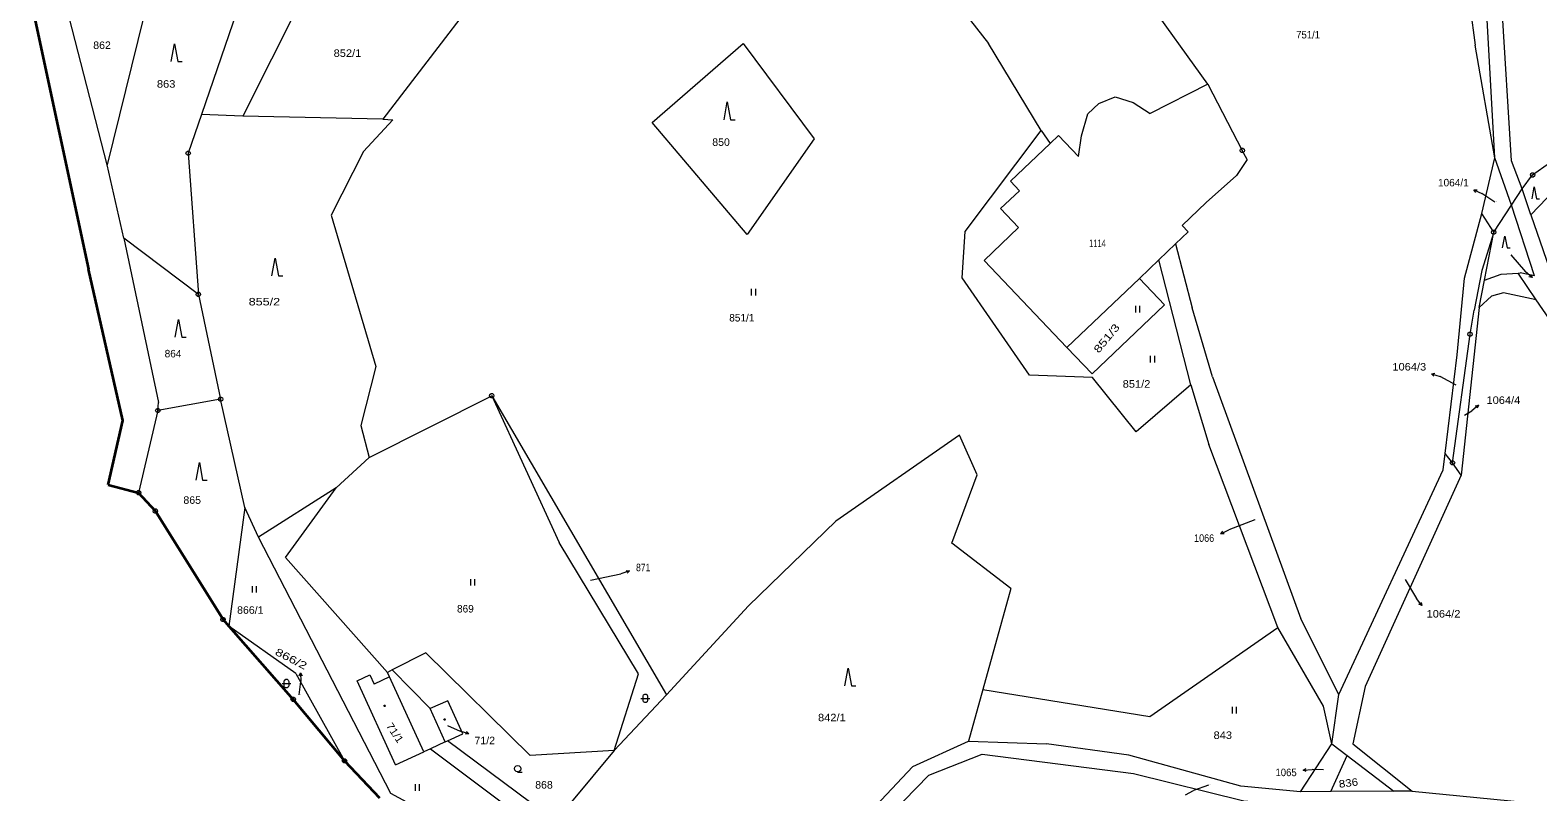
# Model space of a CAD drawing. Extents: x -687390 to -684106, y -954833 to -951648.
# Drawn here: x -687321 to -686980, y -953758.4 to -953586.1 of the extents above; entities that cross this region are included whole.
import ezdxf
from ezdxf.enums import TextEntityAlignment as Align

# ---------------------------------------------------------------- set-up
doc = ezdxf.new("R2010")
doc.units = 0
doc.header["$LTSCALE"] = 0.68
for name, color, linetype, lineweight in [('1', 7, 'Continuous', 13), ('3', 7, 'Continuous', 13), ('4', 7, 'Continuous', 13), ('5', 7, 'Continuous', 13), ('7', 7, 'Continuous', 13), ('8', 7, 'Continuous', 13)]:
    doc.layers.add(name, color=color, linetype=linetype, lineweight=lineweight)
doc.layers.add('2', color=7, linetype='Continuous')

msp = doc.modelspace()

# ---------------------------------------------------------------- linework, layer by layer
at = {"layer": '1'}
for p, q in [((-687122.28, -953566.01), (-687104.26, -953589.16)), ((-687054.67, -953598.36), (-687073.39, -953572.18)), ((-686995.32, -953581.1), (-686994.2, -953589.53)), ((-686989.73, -953615.03), (-686991.62, -953580.99)), ((-687295.24, -953582.94), (-687303.52, -953616.63)), ((-686989.73, -953615.03), (-686994.2, -953589.53)), ((-687054.67, -953598.36), (-687067.72, -953605)), ((-687054.67, -953598.36), (-687046.87, -953613.34)), ((-687071.57, -953602.48), (-687067.72, -953605)), ((-687099.3, -953620.31), (-687090.31, -953611.76)), ((-687088.42, -953609.96), (-687083.89, -953614.72)), ((-687083.89, -953614.72), (-687083.22, -953610.02)), ((-687045.79, -953615.4), (-687048.16, -953618.97)), ((-687045.79, -953615.4), (-687046.87, -953613.34)), ((-686992.69, -953627.63), (-686989.73, -953615.03)), ((-686985.98, -953625.68), (-686989.73, -953615.03)), ((-687299.75, -953633.15), (-687303.52, -953616.63)), ((-687055.01, -953625.1), (-687048.16, -953618.97)), ((-686972.07, -953617.91), (-686981.59, -953627.91)), ((-687101.54, -953626.49), (-687097.28, -953622.44)), ((-687099.3, -953620.31), (-687097.28, -953622.44)), ((-686981.59, -953627.91), (-686983.6, -953622.05)), ((-687101.54, -953626.49), (-687097.45, -953630.78)), ((-686980.79, -953641.68), (-686985.98, -953625.68)), ((-686996.6, -953642.25), (-686992.69, -953627.63)), ((-686990.01, -953631.84), (-686992.69, -953627.63)), ((-686981.59, -953627.91), (-686958.5, -953695.18)), ((-687299.75, -953633.15), (-687291.92, -953670.34)), ((-687105.27, -953638.22), (-687097.45, -953630.78)), ((-687061.95, -953634.5), (-687059.08, -953631.77)), ((-686990.01, -953631.84), (-686992.67, -953640.5)), ((-686992.11, -953642.71), (-686990.01, -953631.84)), ((-687061.95, -953634.5), (-687058.17, -953648.97)), ((-687105.27, -953638.22), (-687086.54, -953657.89)), ((-687070.14, -953642.29), (-687064.46, -953648.25)), ((-686998.3, -953659.55), (-686996.6, -953642.25)), ((-686992.67, -953640.5), (-686994.45, -953649.43)), ((-686992.11, -953642.71), (-686988.33, -953641.36)), ((-686980.39, -953647.15), (-686984.52, -953641.1)), ((-686980.79, -953641.68), (-686984, -953641.06)), ((-687064.46, -953648.25), (-687080.84, -953663.88)), ((-687053.57, -953664.58), (-687058.17, -953648.97)), ((-686995.37, -953654.89), (-686994.45, -953649.43)), ((-687080.84, -953663.88), (-687086.54, -953657.89)), ((-687058.5, -953666.32), (-687054.46, -953679.82)), ((-687053.57, -953664.58), (-687033.66, -953719.27)), ((-687292.1, -953672.19), (-687291.92, -953670.34)), ((-687244.29, -953682.82), (-687216.59, -953668.83)), ((-687216.59, -953668.83), (-687201.33, -953701.99)), ((-687292.1, -953672.19), (-687296.44, -953690.76)), ((-687038.81, -953721.26), (-687054.46, -953679.82)), ((-686999.33, -953684.01), (-687001.03, -953681.87)), ((-687025.07, -953736.37), (-687001.48, -953685.61)), ((-687272.41, -953694.1), (-687276.06, -953720.94)), ((-687177.08, -953736.48), (-687158.53, -953716.37)), ((-687260.9, -953731.67), (-687276.06, -953720.94)), ((-687067.79, -953741.36), (-687038.81, -953721.26)), ((-687260.9, -953731.67), (-687249.88, -953751.4)), ((-687244.16, -953731.95), (-687243.2, -953734.04)), ((-687239.7, -953732.43), (-687240.18, -953731.39)), ((-687239.1, -953730.85), (-687230.48, -953739.6)), ((-687239.7, -953732.43), (-687243.2, -953734.04)), ((-687105.54, -953735.25), (-687067.79, -953741.36)), ((-687226.53, -953737.82), (-687230.48, -953739.6)), ((-687227.1, -953747.12), (-687230.48, -953739.6)), ((-687230.43, -953748.66), (-687203.33, -953768.99)), ((-687227.1, -953747.12), (-687226.6, -953746.9)), ((-687108.81, -953746.95), (-687091.12, -953747.58)), ((-687033.7, -953758.39), (-687026.6, -953747.56)), ((-687238.33, -953752.28), (-687231.94, -953749.35)), ((-687026.82, -953758.35), (-687023.16, -953750.19)), ((-687008.44, -953758.27), (-687012.57, -953758.28))]:
    msp.add_line(p, q, dxfattribs=at)
at = {"layer": '1', "lineweight": 35}
for p, q in [((-687320.97, -953578.62), (-687307.81, -953640.21)), ((-687303.3, -953688.97), (-687296.44, -953690.76)), ((-687292.65, -953694.92), (-687296.44, -953690.76)), ((-687277.36, -953719.45), (-687292.65, -953694.92)), ((-687261.48, -953737.5), (-687249.88, -953751.4)), ((-687249.88, -953751.4), (-687241.94, -953759.8))]:
    msp.add_line(p, q, dxfattribs=at)
at = {"layer": '1'}
for points in [[(-687303.52, -953616.63), (-687313.41, -953578.17), (-687305.51, -953582.02), (-687283.42, -953540.01), (-687248.89, -953494.77)], [(-686983.6, -953622.05), (-686986.01, -953615.7), (-686988.15, -953580.23), (-686986.8, -953544.67), (-686989.72, -953526.06)], [(-687259.89, -953555.79), (-687271.57, -953574.12), (-687282.2, -953605.18), (-687285.23, -953613.98), (-687282.93, -953645.9), (-687299.75, -953633.15)], [(-687209.64, -953564.99), (-687241.21, -953606.29), (-687272.84, -953605.61)], [(-687259.92, -953579.82), (-687272.84, -953605.61), (-687282.2, -953605.18)], [(-687058.5, -953666.32), (-687070.83, -953677), (-687080.73, -953664.72), (-687094.99, -953664.18), (-687110.21, -953642.18), (-687109.53, -953631.68), (-687092.38, -953608.84), (-687104.26, -953589.16)], [(-687083.22, -953610.02), (-687081.77, -953605.09), (-687079.33, -953602.69), (-687075.61, -953601.22), (-687071.57, -953602.48)], [(-687241.21, -953606.29), (-687238.93, -953606.38), (-687245.61, -953613.55), (-687252.92, -953628.01), (-687242.81, -953662.21), (-687246.22, -953675.58), (-687244.29, -953682.82), (-687251.79, -953689.67), (-687269.32, -953700.82), (-687272.41, -953694.1), (-687277.89, -953669.6)], [(-687092.38, -953608.84), (-687090.31, -953611.76), (-687088.42, -953609.96)], [(-686983.6, -953622.05), (-686981.22, -953618.89), (-686972.27, -953612.53)], [(-686990.01, -953631.84), (-686985.98, -953625.68), (-686983.6, -953622.05)], [(-687055.01, -953625.1), (-687060.48, -953630.31), (-687059.08, -953631.77)], [(-687058.5, -953666.32), (-687065.73, -953638.1), (-687061.95, -953634.5)], [(-687086.54, -953657.89), (-687070.14, -953642.29), (-687065.73, -953638.1)], [(-686988.33, -953641.36), (-686984.52, -953641.1), (-686984, -953641.06)], [(-687282.93, -953645.9), (-687277.89, -953669.6), (-687292.1, -953672.19)], [(-686987.83, -953645.51), (-686990.51, -953646.29), (-686993.29, -953648.84), (-686997.39, -953686.82), (-687019.09, -953734.57), (-687021.85, -953747.55), (-687008.44, -953758.27), (-686979.19, -953761.14), (-686963.87, -953771.57), (-686958.4, -953782.31)], [(-686977.42, -953651.49), (-686980.39, -953647.15), (-686987.83, -953645.51)], [(-686997.39, -953686.82), (-686999.33, -953684.01), (-686995.37, -953654.89)], [(-687001.48, -953685.61), (-687001.03, -953681.87), (-686998.3, -953659.55)], [(-687216.59, -953668.83), (-687177.08, -953736.48), (-687188.89, -953749.08), (-687207.88, -953750.21), (-687231.46, -953727.01)], [(-687099.18, -953712.44), (-687112.52, -953702.16), (-687106.8, -953686.69), (-687110.82, -953677.75), (-687138.76, -953697.23), (-687158.53, -953716.37)], [(-687240.18, -953731.39), (-687263.24, -953705.43), (-687251.79, -953689.67)], [(-687186.34, -953779.52), (-687203.33, -953768.99), (-687207.01, -953776.37), (-687239.43, -953758.79), (-687269.32, -953700.82)], [(-687188.89, -953749.08), (-687183.37, -953731.72), (-687201.33, -953701.99)], [(-687099.18, -953712.44), (-687105.54, -953735.25), (-687108.81, -953746.95)], [(-687026.6, -953747.56), (-687028.53, -953739.05), (-687038.81, -953721.26)], [(-687026.6, -953747.56), (-687025.07, -953736.37), (-687033.66, -953719.27)], [(-687231.46, -953727.01), (-687239.1, -953730.85), (-687240.18, -953731.39)], [(-687238.33, -953752.28), (-687247.04, -953733.28), (-687244.16, -953731.95)], [(-687226.6, -953746.9), (-687223.11, -953745.32), (-687226.53, -953737.82)], [(-687227.1, -953747.12), (-687230.43, -953748.66), (-687231.94, -953749.35)], [(-687198.55, -953760.7), (-687201.24, -953765.7), (-687226.6, -953746.9)], [(-687188.89, -953749.08), (-687198.55, -953760.7), (-687173.96, -953778.19)], [(-687161.85, -953777.68), (-687149.8, -953775.92), (-687135.66, -953767.9), (-687121.36, -953752.72), (-687108.81, -953746.95)], [(-687033.7, -953758.39), (-687047.2, -953757.14), (-687072.54, -953750.14), (-687091.12, -953747.58)], [(-687026.6, -953747.56), (-687023.16, -953750.19), (-687012.57, -953758.28)], [(-687148.81, -953779.17), (-687134.53, -953771.88), (-687117.73, -953754.67), (-687105.72, -953749.93), (-687071.47, -953754.3), (-687046.55, -953760.43), (-687028.09, -953761.94)], [(-687012.57, -953758.28), (-687026.82, -953758.35), (-687033.7, -953758.39)]]:
    msp.add_lwpolyline(points, dxfattribs=at)
msp.add_lwpolyline([(-687159.7, -953589.13), (-687143.71, -953610.72), (-687158.81, -953632.33), (-687180.3, -953607.01)], close=True, dxfattribs=at)
at = {"layer": '1', "lineweight": 35}
for points in [[(-687303.3, -953688.97), (-687299.99, -953674.46), (-687307.81, -953640.21)], [(-687277.36, -953719.45), (-687276.06, -953720.94), (-687261.48, -953737.5)]]:
    msp.add_lwpolyline(points, dxfattribs=at)
at = {"layer": '3'}
for p, q in [((-687157.89, -953644.67), (-687157.89, -953646.17)), ((-687156.89, -953646.17), (-687156.89, -953644.67)), ((-687071.01, -953648.49), (-687071.01, -953649.99)), ((-687070.01, -953649.99), (-687070.01, -953648.49)), ((-687067.67, -953659.82), (-687067.67, -953661.32)), ((-687066.67, -953661.32), (-687066.67, -953659.82)), ((-687221.42, -953710.28), (-687221.42, -953711.78)), ((-687220.42, -953711.78), (-687220.42, -953710.28)), ((-687270.76, -953711.86), (-687270.76, -953713.36)), ((-687269.76, -953713.36), (-687269.76, -953711.86)), ((-687049.17, -953739.16), (-687049.17, -953740.66)), ((-687048.17, -953740.66), (-687048.17, -953739.16)), ((-687233.93, -953756.65), (-687233.93, -953758.15)), ((-687232.93, -953758.15), (-687232.93, -953756.65))]:
    msp.add_line(p, q, dxfattribs=at)
for points in [[(-687289.07, -953593.23), (-687288.32, -953589.23), (-687287.57, -953593.23), (-687286.57, -953593.23)], [(-687164.07, -953606.38), (-687163.32, -953602.38), (-687162.57, -953606.38), (-687161.57, -953606.38)], [(-686981.342, -953624.26), (-686980.84, -953621.58), (-686980.338, -953624.26), (-686979.668, -953624.26)], [(-686988.002, -953635.38), (-686987.5, -953632.7), (-686986.998, -953635.38), (-686986.328, -953635.38)], [(-687266.31, -953641.68), (-687265.56, -953637.68), (-687264.81, -953641.68), (-687263.81, -953641.68)], [(-687288.19, -953655.58), (-687287.44, -953651.58), (-687286.69, -953655.58), (-687285.69, -953655.58)], [(-687283.46, -953687.93), (-687282.71, -953683.93), (-687281.96, -953687.93), (-687280.96, -953687.93)], [(-687136.76, -953734.41), (-687136.01, -953730.41), (-687135.26, -953734.41), (-687134.26, -953734.41)], [(-687264.02, -953733.93), (-687262.75, -953733.93), (-687262.02, -953733.93)], [(-687182.85, -953737.27), (-687181.58, -953737.27), (-687180.85, -953737.27)], [(-687210.72, -953753.91), (-687211.1, -953753.81), (-687211.37, -953753.54), (-687211.47, -953753.17), (-687211.37, -953752.8), (-687211.1, -953752.53), (-687210.73, -953752.43), (-687210.36, -953752.53), (-687210.09, -953752.8), (-687209.99, -953753.18), (-687210.09, -953753.56), (-687210.36, -953753.83), (-687210.74, -953753.93), (-687209.74, -953753.93)]]:
    msp.add_lwpolyline(points, dxfattribs=at)
for points in [[(-687263.52, -953733.43), (-687263.42, -953733.14), (-687263.17, -953732.96), (-687262.86, -953732.96), (-687262.61, -953733.14), (-687262.51, -953733.43), (-687262.51, -953734.43), (-687262.61, -953734.72), (-687262.86, -953734.9), (-687263.17, -953734.9), (-687263.42, -953734.72), (-687263.52, -953734.43)], [(-687182.35, -953736.77), (-687182.25, -953736.48), (-687182, -953736.3), (-687181.69, -953736.3), (-687181.44, -953736.48), (-687181.34, -953736.77), (-687181.34, -953737.77), (-687181.44, -953738.06), (-687181.69, -953738.24), (-687182, -953738.24), (-687182.25, -953738.06), (-687182.35, -953737.77)]]:
    msp.add_lwpolyline(points, close=True, dxfattribs=at)
at = {"layer": '4'}
for p, q in [((-686993.29, -953648.84), (-686992.11, -953642.71)), ((-687231.94, -953749.35), (-687239.7, -953732.43))]:
    msp.add_line(p, q, dxfattribs=at)
at = {"layer": '5'}
for points in [[(-687240.73, -953738.8), (-687240.64, -953738.95), (-687240.73, -953739.1), (-687240.91, -953739.1), (-687241, -953738.95), (-687240.91, -953738.8)], [(-687227.17, -953741.87), (-687227.08, -953742.02), (-687227.17, -953742.17), (-687227.35, -953742.17), (-687227.44, -953742.02), (-687227.35, -953741.87)]]:
    msp.add_lwpolyline(points, close=True, dxfattribs=at)
at = {"layer": '7'}
for p, q in [((-686994.491, -953622.26), (-686992.67, -953623.11)), ((-686989.76, -953625.01), (-686992.67, -953623.11)), ((-686986.16, -953636.92), (-686982.84, -953640.78)), ((-686981.327, -953642.103), (-686982.84, -953640.78)), ((-687004.048, -953663.838), (-687002.15, -953664.5)), ((-686998.47, -953666.4), (-687002.15, -953664.5)), ((-686996.65, -953673.23), (-686995, -953672.22)), ((-686993.447, -953670.944), (-686995, -953672.22)), ((-687044, -953696.87), (-687049.95, -953699.12)), ((-687051.712, -953700.088), (-687049.95, -953699.12)), ((-687194.29, -953710.51), (-687187.37, -953709.11)), ((-687185.476, -953708.437), (-687187.37, -953709.11)), ((-687010.07, -953710.35), (-687007.5, -953714.72)), ((-687006.246, -953716.291), (-687007.5, -953714.72)), ((-687259.81, -953731.48), (-687259.77, -953733.49)), ((-687260.13, -953736.5), (-687259.77, -953733.49)), ((-687226.63, -953743.38), (-687223.7, -953744.71)), ((-687221.771, -953745.274), (-687223.7, -953744.71)), ((-687033.092, -953753.505), (-687031.09, -953753.33)), ((-687028.51, -953753.47), (-687031.09, -953753.33)), ((-687059.712, -953759.058), (-687057.94, -953758.11)), ((-687054.54, -953756.87), (-687057.94, -953758.11))]:
    msp.add_line(p, q, dxfattribs=at)
for points in [[(-686994.026, -953622.847), (-686994.491, -953622.26), (-686993.742, -953622.24)], [(-686981.611, -953641.41), (-686981.327, -953642.103), (-686982.052, -953641.914)], [(-687003.526, -953664.375), (-687004.048, -953663.838), (-687003.305, -953663.742)], [(-686994.177, -953671.111), (-686993.447, -953670.944), (-686993.752, -953671.628)], [(-687050.963, -953700.059), (-687051.712, -953700.088), (-687051.286, -953699.471)], [(-687186.22, -953708.345), (-687185.476, -953708.437), (-687185.995, -953708.977)], [(-687006.402, -953715.559), (-687006.246, -953716.291), (-687006.926, -953715.976)], [(-687260.132, -953732.157), (-687259.81, -953731.48), (-687259.462, -953732.144)], [(-687222.32, -953744.764), (-687221.771, -953745.274), (-687222.508, -953745.408)], [(-687032.396, -953753.78), (-687033.092, -953753.505), (-687032.454, -953753.113)]]:
    msp.add_lwpolyline(points, dxfattribs=at)
at = {"layer": '8'}
for p, q in [((-687285.35, -953613.98), (-687285.11, -953613.98)), ((-687046.99, -953613.34), (-687046.75, -953613.34)), ((-686981.34, -953618.89), (-686981.1, -953618.89)), ((-686990.13, -953631.84), (-686989.89, -953631.84)), ((-687283.05, -953645.9), (-687282.81, -953645.9)), ((-686995.49, -953654.89), (-686995.25, -953654.89)), ((-687278.01, -953669.6), (-687277.77, -953669.6)), ((-687216.71, -953668.83), (-687216.47, -953668.83)), ((-687292.22, -953672.19), (-687291.98, -953672.19)), ((-686999.45, -953684.01), (-686999.21, -953684.01)), ((-687296.56, -953690.76), (-687296.32, -953690.76)), ((-687292.77, -953694.92), (-687292.53, -953694.92)), ((-687277.48, -953719.45), (-687277.24, -953719.45)), ((-687261.6, -953737.5), (-687261.36, -953737.5)), ((-687250, -953751.4), (-687249.76, -953751.4))]:
    msp.add_line(p, q, dxfattribs=at)
for points in [[(-687046.72, -953612.86), (-687046.47, -953613.04), (-687046.37, -953613.33), (-687046.47, -953613.62), (-687046.72, -953613.8), (-687047.03, -953613.8), (-687047.28, -953613.62), (-687047.38, -953613.33), (-687047.28, -953613.04), (-687047.03, -953612.86)], [(-687285.08, -953613.5), (-687284.83, -953613.68), (-687284.73, -953613.97), (-687284.83, -953614.26), (-687285.08, -953614.44), (-687285.39, -953614.44), (-687285.64, -953614.26), (-687285.74, -953613.97), (-687285.64, -953613.68), (-687285.39, -953613.5)], [(-686981.07, -953618.41), (-686980.82, -953618.59), (-686980.72, -953618.88), (-686980.82, -953619.17), (-686981.07, -953619.35), (-686981.38, -953619.35), (-686981.63, -953619.17), (-686981.73, -953618.88), (-686981.63, -953618.59), (-686981.38, -953618.41)], [(-686989.86, -953631.36), (-686989.61, -953631.54), (-686989.51, -953631.83), (-686989.61, -953632.12), (-686989.86, -953632.3), (-686990.17, -953632.3), (-686990.42, -953632.12), (-686990.52, -953631.83), (-686990.42, -953631.54), (-686990.17, -953631.36)], [(-687282.78, -953645.42), (-687282.53, -953645.6), (-687282.43, -953645.89), (-687282.53, -953646.18), (-687282.78, -953646.36), (-687283.09, -953646.36), (-687283.34, -953646.18), (-687283.44, -953645.89), (-687283.34, -953645.6), (-687283.09, -953645.42)], [(-686995.22, -953654.41), (-686994.97, -953654.59), (-686994.87, -953654.88), (-686994.97, -953655.17), (-686995.22, -953655.35), (-686995.53, -953655.35), (-686995.78, -953655.17), (-686995.88, -953654.88), (-686995.78, -953654.59), (-686995.53, -953654.41)], [(-687277.74, -953669.12), (-687277.49, -953669.3), (-687277.39, -953669.59), (-687277.49, -953669.88), (-687277.74, -953670.06), (-687278.05, -953670.06), (-687278.3, -953669.88), (-687278.4, -953669.59), (-687278.3, -953669.3), (-687278.05, -953669.12)], [(-687216.44, -953668.35), (-687216.19, -953668.53), (-687216.09, -953668.82), (-687216.19, -953669.11), (-687216.44, -953669.29), (-687216.75, -953669.29), (-687217, -953669.11), (-687217.1, -953668.82), (-687217, -953668.53), (-687216.75, -953668.35)], [(-687291.95, -953671.71), (-687291.7, -953671.89), (-687291.6, -953672.18), (-687291.7, -953672.47), (-687291.95, -953672.65), (-687292.26, -953672.65), (-687292.51, -953672.47), (-687292.61, -953672.18), (-687292.51, -953671.89), (-687292.26, -953671.71)], [(-686999.18, -953683.53), (-686998.93, -953683.71), (-686998.83, -953684), (-686998.93, -953684.29), (-686999.18, -953684.47), (-686999.49, -953684.47), (-686999.74, -953684.29), (-686999.84, -953684), (-686999.74, -953683.71), (-686999.49, -953683.53)], [(-687296.29, -953690.28), (-687296.04, -953690.46), (-687295.94, -953690.75), (-687296.04, -953691.04), (-687296.29, -953691.22), (-687296.6, -953691.22), (-687296.85, -953691.04), (-687296.95, -953690.75), (-687296.85, -953690.46), (-687296.6, -953690.28)], [(-687292.5, -953694.44), (-687292.25, -953694.62), (-687292.15, -953694.91), (-687292.25, -953695.2), (-687292.5, -953695.38), (-687292.81, -953695.38), (-687293.06, -953695.2), (-687293.16, -953694.91), (-687293.06, -953694.62), (-687292.81, -953694.44)], [(-687277.21, -953718.97), (-687276.96, -953719.15), (-687276.86, -953719.44), (-687276.96, -953719.73), (-687277.21, -953719.91), (-687277.52, -953719.91), (-687277.77, -953719.73), (-687277.87, -953719.44), (-687277.77, -953719.15), (-687277.52, -953718.97)], [(-687261.33, -953737.02), (-687261.08, -953737.2), (-687260.98, -953737.49), (-687261.08, -953737.78), (-687261.33, -953737.96), (-687261.64, -953737.96), (-687261.89, -953737.78), (-687261.99, -953737.49), (-687261.89, -953737.2), (-687261.64, -953737.02)], [(-687249.73, -953750.92), (-687249.48, -953751.1), (-687249.38, -953751.39), (-687249.48, -953751.68), (-687249.73, -953751.86), (-687250.04, -953751.86), (-687250.29, -953751.68), (-687250.39, -953751.39), (-687250.29, -953751.1), (-687250.04, -953750.92)]]:
    msp.add_lwpolyline(points, close=True, dxfattribs=at)

# ---------------------------------------------------------------- texts
at = {"layer": '2'}
for s, height, width, p in [('862', 1.7, 1.05, (-687306.705, -953590.39)), ('751/1', 1.7, 0.95, (-687034.685, -953588.01)), ('852/1', 1.7, 1.1, (-687252.345, -953592.18)), ('863', 1.7, 1.1, (-687292.305, -953599.15)), ('850', 1.7, 1.05, (-687166.725, -953612.31)), ('1114', 1.7, 0.65, (-687081.495, -953635.19)), ('834/2', 0.1, 1.25, (-686986.132, -953636.92)), ('855/2', 1.7, 1.25, (-687271.555, -953648.4)), ('851/2', 1.7, 1.1, (-687073.915, -953667)), ('1064/3', 0.1, 1.1, (-686998.424, -953666.4)), ('1064/4', 0.1, 1.1, (-686996.604, -953673.23)), ('865', 1.7, 1.05, (-687286.315, -953693.27)), ('1066', 0.1, 0.9, (-687043.954, -953696.87)), ('871', 0.1, 0.85, (-687194.262, -953710.51)), ('1064/2', 0.1, 1.1, (-687010.024, -953710.35)), ('866/1', 1.7, 1.05, (-687274.175, -953718.14)), ('866/2', 0.1, 1.2, (-687260.102, -953736.5)), ('842/1', 1.7, 1.1, (-687142.805, -953742.46)), ('71/2', 0.1, 1.05, (-687226.602, -953743.38)), ('843', 1.7, 1.1, (-687053.365, -953746.45)), ('868', 1.7, 1.05, (-687206.765, -953757.68)), ('1065', 0.1, 0.95, (-687028.464, -953753.47)), ('1059/3', 0.1, 1.1, (-687054.494, -953756.87))]:
    msp.add_text(s, height=height, dxfattribs=dict(at, width=width)).set_placement(p)
for s, height, p in [('1064/1', 0.1, (-686989.714, -953625.01)), ('851/1', 1.7, (-687162.885, -953652.03)), ('864', 1.7, (-687290.555, -953660.15)), ('869', 1.7, (-687224.445, -953717.85))]:
    msp.add_text(s, height=height, dxfattribs=at).set_placement(p)
for s, rotation, width, p in [('851/3', 50.535, 1.35, (-687079.338, -953659.333)), ('71/1', 303.897, 1.1, (-687240.555, -953743.514)), ('836', 7.162, 1.15, (-687024.929, -953757.511))]:
    msp.add_text(s, height=1.7, rotation=rotation, dxfattribs=dict(at, width=width)).set_placement(p)
at = {"layer": '7'}
msp.add_text('1064/1', height=1.7, dxfattribs=at).set_placement((-686995.666, -953621.47), align=Align.RIGHT)
for s, width, p in [('1064/3', 1.1, (-687005.286, -953663.12)), ('1066', 0.9, (-687053.226, -953701.87)), ('1065', 0.95, (-687034.566, -953754.87))]:
    msp.add_text(s, height=1.7, dxfattribs=dict(at, width=width)).set_placement(p, align=Align.RIGHT)
for s, width, p in [('1064/4', 1.1, (-686991.645, -953670.67)), ('871', 0.85, (-687183.955, -953708.51)), ('1064/2', 1.1, (-687005.195, -953719)), ('71/2', 1.05, (-687220.495, -953747.65))]:
    msp.add_text(s, height=1.7, dxfattribs=dict(at, width=width)).set_placement(p)
at = {"layer": '7', "width": 1.35}
msp.add_text('866/2', height=1.7, rotation=332.831, dxfattribs=at).set_placement((-687258.917, -953730.831), align=Align.RIGHT)

doc.saveas('drawing.dxf')
